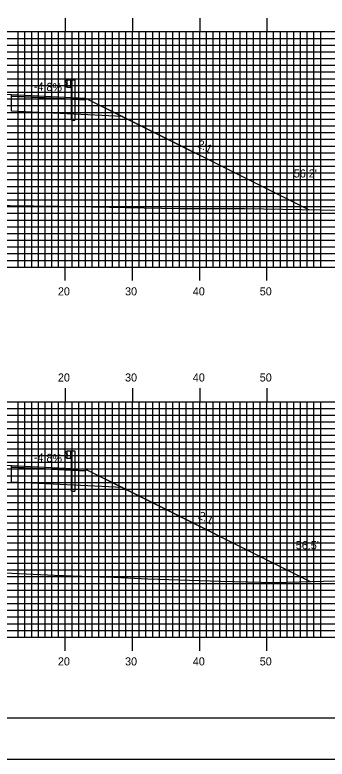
# Model space of a CAD drawing. Extents: x 1811767 to 1812110, y 442591 to 442811.
# Drawn here: x 1811945.4 to 1811991.9, y 442590.5 to 442701.2 of the extents above; entities that cross this region are included whole.
import ezdxf

# ---------------------------------------------------------------- set-up
doc = ezdxf.new("R2010")
doc.units = 0
for name, color, linetype in [('ANNOTATION', 7, 'Continuous'), ('BORDER', 7, 'Continuous'), ('D_Guardrail_Beam_Rt', 7, 'Continuous'), ('D_Roadway_Centerline', 7, 'Continuous'), ('D_Roadway_Edge_Shoulder', 7, 'Continuous'), ('D_Roadway_SlopeLines', 7, 'Continuous'), ('D_Roadway_SubGrade', 7, 'Continuous'), ('D_Text_Standard', 7, 'Continuous'), ('H_V ANNOTATION', 7, 'Continuous'), ('MAJOR', 7, 'Continuous'), ('MINOR', 7, 'Continuous'), ('PLOT BOUNDARY', 7, 'Continuous'), ('S_Roadway_Centerline', 7, 'Continuous')]:
    doc.layers.add(name, color=color, linetype=linetype)

msp = doc.modelspace()

# ---------------------------------------------------------------- linework, layer by layer
at = {"layer": 'BORDER'}
msp.add_lwpolyline([(1811783.32, 442596.67), (1812103.32, 442596.67), (1812103.32, 442806.67), (1811783.32, 442806.67)], close=True, dxfattribs=at)
at = {"layer": 'D_Guardrail_Beam_Rt'}
for p, q in [((1811953.19, 442691.53), (1811953.87, 442691.53)), ((1811953.19, 442690.36), (1811953.19, 442691.53)), ((1811953.71, 442691.53), (1811953.71, 442690.36)), ((1811953.81, 442691.53), (1811953.81, 442690.36)), ((1811953.87, 442691.53), (1811954.35, 442691.53)), ((1811953.87, 442691.53), (1811953.87, 442690.36)), ((1811954.35, 442691.53), (1811954.35, 442685.53)), ((1811953.1, 442691.42), (1811952.95, 442691.32)), ((1811952.95, 442691.18), (1811953.15, 442691.05)), ((1811953.15, 442690.85), (1811952.95, 442690.71)), ((1811952.95, 442690.57), (1811953.1, 442690.47)), ((1811953.19, 442691.45), (1811953.11, 442691.43)), ((1811953.11, 442690.46), (1811953.19, 442690.45)), ((1811953.18, 442690.98), (1811953.18, 442690.91)), ((1811953.87, 442690.36), (1811953.19, 442690.36)), ((1811953.85, 442685.53), (1811953.85, 442690.36)), ((1811953.85, 442685.53), (1811954.35, 442685.53)), ((1811953.1, 442636.29), (1811952.95, 442636.19)), ((1811953.19, 442636.31), (1811953.11, 442636.29)), ((1811953.19, 442636.39), (1811953.87, 442636.39)), ((1811953.19, 442635.22), (1811953.19, 442636.39)), ((1811953.71, 442636.39), (1811953.71, 442635.22)), ((1811953.81, 442636.39), (1811953.81, 442635.22)), ((1811953.87, 442636.39), (1811954.35, 442636.39)), ((1811953.87, 442636.39), (1811953.87, 442635.22)), ((1811954.35, 442636.39), (1811954.35, 442630.39)), ((1811952.95, 442636.04), (1811953.15, 442635.91)), ((1811953.15, 442635.71), (1811952.95, 442635.57)), ((1811952.95, 442635.43), (1811953.1, 442635.33)), ((1811953.11, 442635.32), (1811953.19, 442635.31)), ((1811953.18, 442635.84), (1811953.18, 442635.77)), ((1811953.87, 442635.22), (1811953.19, 442635.22)), ((1811953.85, 442630.39), (1811953.85, 442635.22)), ((1811953.85, 442630.39), (1811954.35, 442630.39))]:
    msp.add_line(p, q, dxfattribs=at)
for centre, major_axis, start_param, end_param in [((1811953, 442691.25), (-0.0877, 0), 5.323254, 7.243116), ((1811953, 442690.64), (-0.0877, 0), 5.323254, 7.243116), ((1811953.12, 442691.39), (-0.0417, 0), 4.907132, 5.323254), ((1811953.12, 442690.5), (-0.0417, 0), 0.959931, 1.376053), ((1811953.1, 442690.98), (0.0789, 0), 0, 0.959931), ((1811953.1, 442690.91), (0.0789, 0), 5.323254, 6.283185), ((1811953.12, 442636.25), (-0.0417, 0), 4.907132, 5.323254), ((1811953, 442636.11), (-0.0877, 0), 5.323254, 7.243116), ((1811953, 442635.5), (-0.0877, 0), 5.323254, 7.243116), ((1811953.12, 442635.36), (-0.0417, 0), 0.959931, 1.376053), ((1811953.1, 442635.84), (0.0789, 0), 0, 0.959931), ((1811953.1, 442635.77), (0.0789, 0), 5.323254, 6.283185)]:
    msp.add_ellipse(centre, major_axis=major_axis, ratio=0.995501, start_param=start_param, end_param=end_param, dxfattribs=at)
at = {"layer": 'D_Roadway_Centerline'}
for points in [[(1811878.79, 442674.7), (1811904.71, 442687.66), (1811909.92, 442690.26), (1811912.92, 442690.32), (1811920.92, 442690.48), (1811932.92, 442689.91), (1811944.92, 442689.33), (1811952.92, 442688.95), (1811955.92, 442688.8), (1811961.45, 442686.04), (1811989.08, 442672.22)], [(1811876.82, 442618.58), (1811904.71, 442632.52), (1811909.92, 442635.12), (1811912.92, 442635.18), (1811920.92, 442635.34), (1811932.92, 442634.77), (1811944.92, 442634.19), (1811952.92, 442633.81), (1811955.92, 442633.66), (1811961.45, 442630.9), (1811989.37, 442616.93)]]:
    msp.add_lwpolyline(points, dxfattribs=at)
at = {"layer": 'D_Roadway_Edge_Shoulder'}
for points in [[(1811944.92, 442689.33), (1811952.92, 442688.95), (1811952.92, 442688.95), (1811955.92, 442688.8), (1811955.92, 442688.55), (1811944.92, 442689.08)], [(1811944.92, 442634.19), (1811952.92, 442633.81), (1811952.92, 442633.81), (1811955.92, 442633.66), (1811955.92, 442633.41), (1811944.92, 442633.94)]]:
    msp.add_lwpolyline(points, close=True, dxfattribs=at)
at = {"layer": 'D_Roadway_SlopeLines'}
for points in [[(1811955.92, 442688.8), (1811989.08, 442672.22)], [(1811955.92, 442633.66), (1811989.37, 442616.93)]]:
    msp.add_lwpolyline(points, dxfattribs=at)
at = {"layer": 'D_Roadway_SubGrade'}
for points in [[(1811944.92, 442688.66), (1811944.92, 442689.08), (1811955.92, 442688.55), (1811955.92, 442688.8), (1811961.45, 442686.04), (1811944.92, 442686.83)], [(1811944.92, 442633.52), (1811944.92, 442633.94), (1811955.92, 442633.41), (1811955.92, 442633.66), (1811961.45, 442630.9), (1811944.92, 442631.69)]]:
    msp.add_lwpolyline(points, close=True, dxfattribs=at)
at = {"layer": 'MAJOR'}
for p, q in [((1811952.92, 442700.67), (1811952.92, 442698.67)), ((1811962.92, 442700.67), (1811962.92, 442698.67)), ((1811972.92, 442700.67), (1811972.92, 442698.67)), ((1811982.92, 442700.67), (1811982.92, 442698.67)), ((1811792.92, 442698.67), (1812072.92, 442698.67)), ((1811792.92, 442698.67), (1812072.92, 442698.67)), ((1811952.92, 442663.67), (1811952.92, 442698.67)), ((1811962.92, 442663.67), (1811962.92, 442698.67)), ((1811972.92, 442663.67), (1811972.92, 442698.67)), ((1811982.92, 442663.67), (1811982.92, 442698.67)), ((1811792.92, 442693.67), (1812072.92, 442693.67)), ((1811792.92, 442688.67), (1812072.92, 442688.67)), ((1811792.92, 442683.67), (1812072.92, 442683.67)), ((1811792.92, 442678.67), (1812072.92, 442678.67)), ((1811792.92, 442673.67), (1812072.92, 442673.67)), ((1811792.92, 442668.67), (1812072.92, 442668.67)), ((1811792.92, 442663.67), (1812072.92, 442663.67)), ((1811792.92, 442663.67), (1812072.92, 442663.67)), ((1811952.92, 442661.66), (1811952.92, 442663.67)), ((1811962.92, 442661.66), (1811962.92, 442663.67)), ((1811972.92, 442661.66), (1811972.92, 442663.67)), ((1811982.92, 442661.66), (1811982.92, 442663.67)), ((1811952.92, 442645.67), (1811952.92, 442643.67)), ((1811962.92, 442645.67), (1811962.92, 442643.67)), ((1811972.92, 442645.67), (1811972.92, 442643.67)), ((1811982.92, 442645.67), (1811982.92, 442643.67)), ((1811792.92, 442643.67), (1812072.92, 442643.67)), ((1811792.92, 442643.67), (1812072.92, 442643.67)), ((1811952.92, 442608.67), (1811952.92, 442643.67)), ((1811962.92, 442608.67), (1811962.92, 442643.67)), ((1811972.92, 442608.67), (1811972.92, 442643.67)), ((1811982.92, 442608.67), (1811982.92, 442643.67)), ((1811792.92, 442638.67), (1812072.92, 442638.67)), ((1811792.92, 442633.67), (1812072.92, 442633.67)), ((1811792.92, 442628.67), (1812072.92, 442628.67)), ((1811792.92, 442623.67), (1812072.92, 442623.67)), ((1811792.92, 442618.67), (1812072.92, 442618.67)), ((1811792.92, 442613.67), (1812072.92, 442613.67)), ((1811792.92, 442608.67), (1812072.92, 442608.67)), ((1811792.92, 442608.67), (1812072.92, 442608.67)), ((1811952.92, 442606.66), (1811952.92, 442608.67)), ((1811962.92, 442606.66), (1811962.92, 442608.67)), ((1811972.92, 442606.66), (1811972.92, 442608.67)), ((1811982.92, 442606.66), (1811982.92, 442608.67))]:
    msp.add_line(p, q, dxfattribs=at)
at = {"layer": 'MINOR'}
for p, q in [((1811945.92, 442663.67), (1811945.92, 442698.67)), ((1811946.92, 442663.67), (1811946.92, 442698.67)), ((1811947.92, 442663.67), (1811947.92, 442698.67)), ((1811948.92, 442663.67), (1811948.92, 442698.67)), ((1811949.92, 442663.67), (1811949.92, 442698.67)), ((1811950.92, 442663.67), (1811950.92, 442698.67)), ((1811951.92, 442663.67), (1811951.92, 442698.67)), ((1811953.92, 442663.67), (1811953.92, 442698.67)), ((1811954.92, 442663.67), (1811954.92, 442698.67)), ((1811955.92, 442663.67), (1811955.92, 442698.67)), ((1811956.92, 442663.67), (1811956.92, 442698.67)), ((1811957.92, 442663.67), (1811957.92, 442698.67)), ((1811958.92, 442663.67), (1811958.92, 442698.67)), ((1811959.92, 442663.67), (1811959.92, 442698.67)), ((1811960.92, 442663.67), (1811960.92, 442698.67)), ((1811961.92, 442663.67), (1811961.92, 442698.67)), ((1811963.92, 442663.67), (1811963.92, 442698.67)), ((1811964.92, 442663.67), (1811964.92, 442698.67)), ((1811965.92, 442663.67), (1811965.92, 442698.67)), ((1811966.92, 442663.67), (1811966.92, 442698.67)), ((1811967.92, 442663.67), (1811967.92, 442698.67)), ((1811968.92, 442663.67), (1811968.92, 442698.67)), ((1811969.92, 442663.67), (1811969.92, 442698.67)), ((1811970.92, 442663.67), (1811970.92, 442698.67)), ((1811971.92, 442663.67), (1811971.92, 442698.67)), ((1811973.92, 442663.67), (1811973.92, 442698.67)), ((1811974.92, 442663.67), (1811974.92, 442698.67)), ((1811975.92, 442663.67), (1811975.92, 442698.67)), ((1811976.92, 442663.67), (1811976.92, 442698.67)), ((1811977.92, 442663.67), (1811977.92, 442698.67)), ((1811978.92, 442663.67), (1811978.92, 442698.67)), ((1811979.92, 442663.67), (1811979.92, 442698.67)), ((1811980.92, 442663.67), (1811980.92, 442698.67)), ((1811981.92, 442663.67), (1811981.92, 442698.67)), ((1811983.92, 442663.67), (1811983.92, 442698.67)), ((1811984.92, 442663.67), (1811984.92, 442698.67)), ((1811985.92, 442663.67), (1811985.92, 442698.67)), ((1811986.92, 442663.67), (1811986.92, 442698.67)), ((1811987.92, 442663.67), (1811987.92, 442698.67)), ((1811988.92, 442663.67), (1811988.92, 442698.67)), ((1811989.92, 442663.67), (1811989.92, 442698.67)), ((1811990.92, 442663.67), (1811990.92, 442698.67)), ((1811792.92, 442697.67), (1812072.92, 442697.67)), ((1811792.92, 442696.67), (1812072.92, 442696.67)), ((1811792.92, 442695.67), (1812072.92, 442695.67)), ((1811792.92, 442694.67), (1812072.92, 442694.67)), ((1811792.92, 442692.67), (1812072.92, 442692.67)), ((1811792.92, 442691.67), (1812072.92, 442691.67)), ((1811792.92, 442690.67), (1812072.92, 442690.67)), ((1811792.92, 442689.67), (1812072.92, 442689.67)), ((1811792.92, 442687.67), (1812072.92, 442687.67)), ((1811792.92, 442686.67), (1812072.92, 442686.67)), ((1811792.92, 442685.67), (1812072.92, 442685.67)), ((1811792.92, 442684.67), (1812072.92, 442684.67)), ((1811792.92, 442682.67), (1812072.92, 442682.67)), ((1811792.92, 442681.67), (1812072.92, 442681.67)), ((1811792.92, 442680.67), (1812072.92, 442680.67)), ((1811792.92, 442679.67), (1812072.92, 442679.67)), ((1811792.92, 442677.67), (1812072.92, 442677.67)), ((1811792.92, 442676.67), (1812072.92, 442676.67)), ((1811792.92, 442675.67), (1812072.92, 442675.67)), ((1811792.92, 442674.67), (1812072.92, 442674.67)), ((1811792.92, 442672.67), (1812072.92, 442672.67)), ((1811792.92, 442671.67), (1812072.92, 442671.67)), ((1811792.92, 442670.67), (1812072.92, 442670.67)), ((1811792.92, 442669.67), (1812072.92, 442669.67)), ((1811792.92, 442667.67), (1812072.92, 442667.67)), ((1811792.92, 442666.67), (1812072.92, 442666.67)), ((1811792.92, 442665.67), (1812072.92, 442665.67)), ((1811792.92, 442664.67), (1812072.92, 442664.67)), ((1811945.92, 442608.67), (1811945.92, 442643.67)), ((1811946.92, 442608.67), (1811946.92, 442643.67)), ((1811947.92, 442608.67), (1811947.92, 442643.67)), ((1811948.92, 442608.67), (1811948.92, 442643.67)), ((1811949.92, 442608.67), (1811949.92, 442643.67)), ((1811950.92, 442608.67), (1811950.92, 442643.67)), ((1811951.92, 442608.67), (1811951.92, 442643.67)), ((1811953.92, 442608.67), (1811953.92, 442643.67)), ((1811954.92, 442608.67), (1811954.92, 442643.67)), ((1811955.92, 442608.67), (1811955.92, 442643.67)), ((1811956.92, 442608.67), (1811956.92, 442643.67)), ((1811957.92, 442608.67), (1811957.92, 442643.67)), ((1811958.92, 442608.67), (1811958.92, 442643.67)), ((1811959.92, 442608.67), (1811959.92, 442643.67)), ((1811960.92, 442608.67), (1811960.92, 442643.67)), ((1811961.92, 442608.67), (1811961.92, 442643.67)), ((1811963.92, 442608.67), (1811963.92, 442643.67)), ((1811964.92, 442608.67), (1811964.92, 442643.67)), ((1811965.92, 442608.67), (1811965.92, 442643.67)), ((1811966.92, 442608.67), (1811966.92, 442643.67)), ((1811967.92, 442608.67), (1811967.92, 442643.67)), ((1811968.92, 442608.67), (1811968.92, 442643.67)), ((1811969.92, 442608.67), (1811969.92, 442643.67)), ((1811970.92, 442608.67), (1811970.92, 442643.67)), ((1811971.92, 442608.67), (1811971.92, 442643.67)), ((1811973.92, 442608.67), (1811973.92, 442643.67)), ((1811974.92, 442608.67), (1811974.92, 442643.67)), ((1811975.92, 442608.67), (1811975.92, 442643.67)), ((1811976.92, 442608.67), (1811976.92, 442643.67)), ((1811977.92, 442608.67), (1811977.92, 442643.67)), ((1811978.92, 442608.67), (1811978.92, 442643.67)), ((1811979.92, 442608.67), (1811979.92, 442643.67)), ((1811980.92, 442608.67), (1811980.92, 442643.67)), ((1811981.92, 442608.67), (1811981.92, 442643.67)), ((1811983.92, 442608.67), (1811983.92, 442643.67)), ((1811984.92, 442608.67), (1811984.92, 442643.67)), ((1811985.92, 442608.67), (1811985.92, 442643.67)), ((1811986.92, 442608.67), (1811986.92, 442643.67)), ((1811987.92, 442608.67), (1811987.92, 442643.67)), ((1811988.92, 442608.67), (1811988.92, 442643.67)), ((1811989.92, 442608.67), (1811989.92, 442643.67)), ((1811990.92, 442608.67), (1811990.92, 442643.67)), ((1811792.92, 442642.67), (1812072.92, 442642.67)), ((1811792.92, 442641.67), (1812072.92, 442641.67)), ((1811792.92, 442640.67), (1812072.92, 442640.67)), ((1811792.92, 442639.67), (1812072.92, 442639.67)), ((1811792.92, 442637.67), (1812072.92, 442637.67)), ((1811792.92, 442636.67), (1812072.92, 442636.67)), ((1811792.92, 442635.67), (1812072.92, 442635.67)), ((1811792.92, 442634.67), (1812072.92, 442634.67)), ((1811792.92, 442632.67), (1812072.92, 442632.67)), ((1811792.92, 442631.67), (1812072.92, 442631.67)), ((1811792.92, 442630.67), (1812072.92, 442630.67)), ((1811792.92, 442629.67), (1812072.92, 442629.67)), ((1811792.92, 442627.67), (1812072.92, 442627.67)), ((1811792.92, 442626.67), (1812072.92, 442626.67)), ((1811792.92, 442625.67), (1812072.92, 442625.67)), ((1811792.92, 442624.67), (1812072.92, 442624.67)), ((1811792.92, 442622.67), (1812072.92, 442622.67)), ((1811792.92, 442621.67), (1812072.92, 442621.67)), ((1811792.92, 442620.67), (1812072.92, 442620.67)), ((1811792.92, 442619.67), (1812072.92, 442619.67)), ((1811792.92, 442617.67), (1812072.92, 442617.67)), ((1811792.92, 442616.67), (1812072.92, 442616.67)), ((1811792.92, 442615.67), (1812072.92, 442615.67)), ((1811792.92, 442614.67), (1812072.92, 442614.67)), ((1811792.92, 442612.67), (1812072.92, 442612.67)), ((1811792.92, 442611.67), (1812072.92, 442611.67)), ((1811792.92, 442610.67), (1812072.92, 442610.67)), ((1811792.92, 442609.67), (1812072.92, 442609.67))]:
    msp.add_line(p, q, dxfattribs=at)
at = {"layer": 'PLOT BOUNDARY'}
msp.add_lwpolyline([(1811767.13, 442590.55), (1812107.13, 442590.55), (1812107.13, 442810.55), (1811767.13, 442810.55)], close=True, dxfattribs=at)
at = {"layer": 'S_Roadway_Centerline'}
for points in [[(1811792.92, 442675.29), (1811793.32, 442675.31), (1811798.45, 442675.57), (1811809.64, 442675.71), (1811818.69, 442675.7), (1811828.62, 442675.81), (1811833.93, 442675.93), (1811840.94, 442675.65), (1811851.46, 442674.96), (1811854.3, 442674.89), (1811861.95, 442674.83), (1811870.61, 442674.79), (1811880.53, 442674.68), (1811891.99, 442674.77), (1811903.84, 442674.62), (1811919.63, 442673.92), (1811927.29, 442673.55), (1811944.65, 442672.84), (1811951.76, 442672.74), (1811969.82, 442672.4), (1811979.59, 442672.39), (1811993.71, 442672.13)], [(1811870, 442618.46), (1811884.1, 442618.7), (1811888.51, 442618.47), (1811901.52, 442618.74), (1811917.28, 442618.87), (1811920.11, 442618.9), (1811923.12, 442618.97), (1811928.49, 442618.7), (1811936.28, 442618.54), (1811939.65, 442618.42), (1811951.32, 442617.88), (1811958.09, 442617.63), (1811960.18, 442617.58), (1811965.22, 442617.36), (1811976.05, 442617), (1811984.1, 442616.8), (1811994.98, 442617.07)]]:
    msp.add_lwpolyline(points, dxfattribs=at)

# ---------------------------------------------------------------- texts
at = {"layer": 'ANNOTATION'}
for s, rotation, p in [('-4.8%', 357.2519, (1811948.22, 442689.97)), ('2:1', 333.4349, (1811972.43, 442681.58)), ('-4.8%', 357.2519, (1811948.22, 442634.83)), ('2:1', 333.4349, (1811972.58, 442626.37))]:
    msp.add_text(s, height=1.2, rotation=rotation, dxfattribs=at).set_placement(p)
at = {"layer": 'D_Text_Standard'}
for s, p in [("56.2'", (1811986.91, 442676.99)), ("56.5'", (1811987.21, 442621.74))]:
    msp.add_text(s, height=1.2, dxfattribs=at).set_placement(p)
at = {"layer": 'H_V ANNOTATION'}
for s, p in [('20', (1811951.82, 442659.47)), ('30', (1811961.81, 442659.47)), ('40', (1811971.89, 442659.47)), ('50', (1811981.85, 442659.47)), ('20', (1811951.82, 442646.67)), ('30', (1811961.81, 442646.67)), ('40', (1811971.89, 442646.67)), ('50', (1811981.85, 442646.67)), ('20', (1811951.82, 442604.47)), ('30', (1811961.81, 442604.47)), ('40', (1811971.89, 442604.47)), ('50', (1811981.85, 442604.47))]:
    msp.add_text(s, height=1.2, dxfattribs=at).set_placement(p)

doc.saveas('drawing.dxf')
